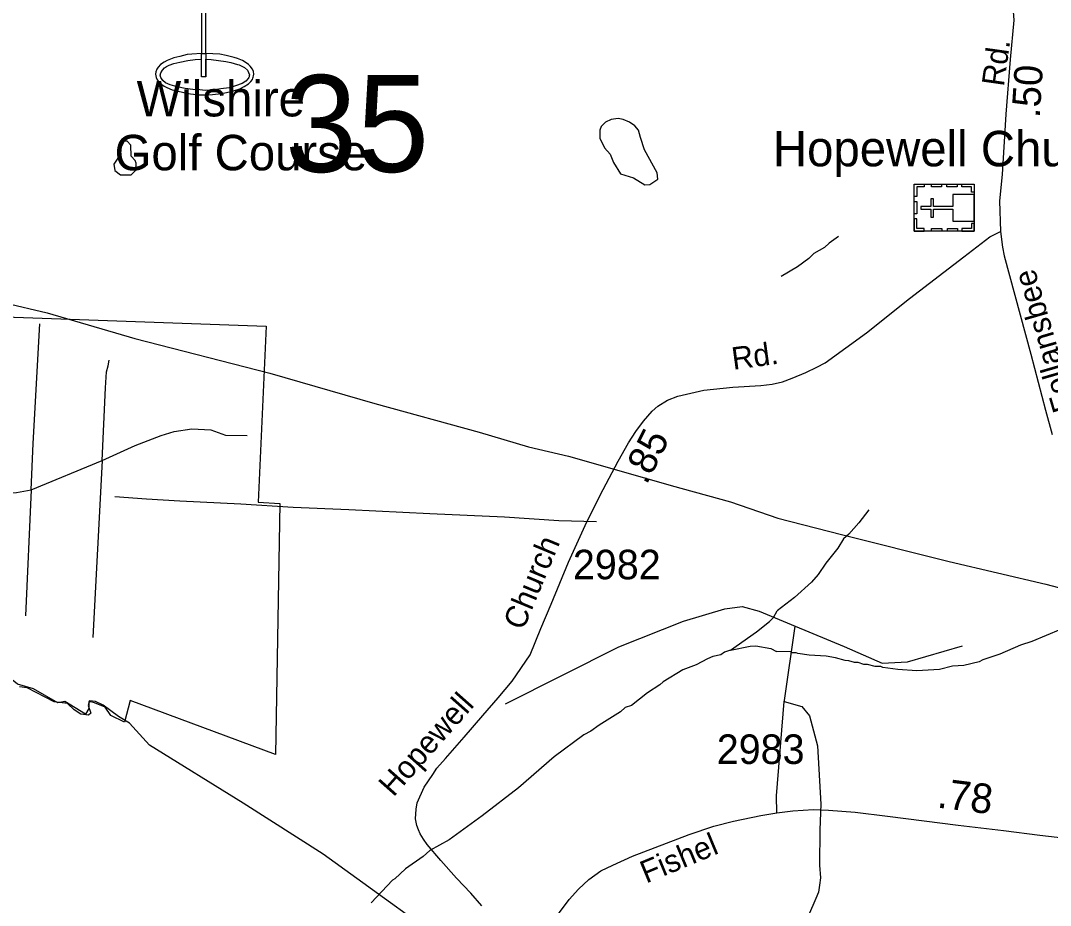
# Model space of a CAD drawing. Extents: x 1547597 to 1699558, y 810033 to 920809.
# Drawn here: x 1627167 to 1631529, y 823409 to 827154 of the extents above; entities that cross this region are included whole.
import ezdxf

# ---------------------------------------------------------------- set-up
doc = ezdxf.new("R2010")
doc.units = 0
for name, color, linetype in [('Exist Boundary Political City Limit New', 7, 'Continuous'), ('Exist Cultural Church with Cemetery CELL', 7, 'Continuous'), ('Exist Cultural Church with Cemetery Label', 7, 'Continuous'), ('Exist Cultural Recreational Golf Course CELL', 7, 'Continuous'), ('Exist Cultural Recreational Golf Course Label', 7, 'Continuous'), ('Exist Hydrographic Creek Single Shore', 7, 'Continuous'), ('Exist Hydrographic Misc Water Feature', 7, 'Continuous'), ('Exist Road Non-System Type 51', 7, 'Continuous'), ('Exist Road Secondary Mileage Hundredths English Label', 7, 'Continuous'), ('Exist Road Secondary Structure Standard Bridge Number Label', 7, 'Continuous'), ('Exist Road Secondary Type 51 Attributed', 7, 'Continuous'), ('Exist Road Secondary Type 51 Label', 7, 'Continuous'), ('Exist Road Secondary Type 51 Number Label', 7, 'Continuous'), ('Exist Utilities Electrical Transmission Line', 7, 'Continuous'), ('Map Preparation Boundary City Limit Buffer Line', 7, 'Continuous')]:
    doc.layers.add(name, color=color, linetype=linetype)

msp = doc.modelspace()

# ---------------------------------------------------------------- linework, layer by layer
at = {"layer": 'Exist Boundary Political City Limit New'}
msp.add_lwpolyline([(1627100, 825900), (1628206.7, 825861), (1628172.5, 825115), (1628265.2, 825110.1), (1628245.7, 824047.1), (1627631.4, 824276.3), (1627607, 824183.6), (1627548.5, 824212.9), (1627524.2, 824247), (1627480.3, 824266.5), (1627455.9, 824271.4), (1627455.9, 824242.2), (1627441.3, 824217.8), (1627353.5, 824271.4), (1627324.3, 824266.5), (1627221.9, 824325.1), (1627153.7, 824344.6), (1627031.8, 824442.1), (1627100, 825900)], dxfattribs=at)
at = {"layer": 'Exist Cultural Church with Cemetery CELL'}
for points in [[(1630951.1, 826262.4), (1630951.1, 826461.4), (1631205.8, 826461.4), (1631205.8, 826262.4)], [(1630994.5, 826461.5), (1630994.5, 826450.2), (1630962.3, 826450.2), (1630962.3, 826409.6), (1630951.2, 826409.6), (1630951.2, 826461.5)], [(1631067.6, 826450.1), (1631024.3, 826450.1), (1631024.3, 826461.5), (1631067.6, 826461.5)], [(1631133.5, 826450.1), (1631090.2, 826450.1), (1631090.2, 826461.5), (1631133.5, 826461.5)], [(1631205.8, 826428.3), (1631194.3, 826428.3), (1631194.3, 826450.3), (1631153.9, 826450.3), (1631153.9, 826461.4), (1631205.8, 826461.4)], [(1631205.7, 826305.5), (1631205.7, 826417.6), (1631115.2, 826417.6), (1631115.1, 826366.9), (1631033.7, 826366.8), (1631033.7, 826399.8), (1631022.7, 826399.8), (1631022.7, 826366.8), (1630980.4, 826366.9), (1630980.4, 826355.3), (1631022.7, 826355.2), (1631022.7, 826322.1), (1631033.7, 826322.1), (1631033.7, 826355.2), (1631115.1, 826355.3), (1631115.2, 826305.5)], [(1630951.1, 826336.4), (1630951.1, 826388.3), (1630962.5, 826388.3), (1630962.5, 826336.4)], [(1630994.4, 826262.4), (1630994.4, 826273.7), (1630962.2, 826273.7), (1630962.3, 826314.3), (1630951.1, 826314.3), (1630951.1, 826262.4)], [(1631205.7, 826295.4), (1631194.2, 826295.4), (1631194.2, 826273.4), (1631153.8, 826273.4), (1631153.8, 826262.3), (1631205.7, 826262.3)], [(1631068.6, 826262.3), (1631025.3, 826262.3), (1631025.3, 826273.7), (1631068.6, 826273.7)], [(1631135.8, 826262.3), (1631092.5, 826262.3), (1631092.5, 826273.7), (1631135.8, 826273.7)]]:
    msp.add_lwpolyline(points, close=True, dxfattribs=at)
at = {"layer": 'Exist Cultural Recreational Golf Course CELL'}
msp.add_lwpolyline([(1627932.4, 827194.1), (1627932.4, 827015.2), (1627950.8, 827015.2), (1627950.8, 826990.2), (1627950.8, 826915.2), (1627950.8, 826990.2), (1627974.5, 826988.6), (1628005, 826985.3), (1628036.5, 826981.3), (1628057.7, 826977), (1628085.5, 826968.7), (1628092.5, 826966.6), (1628115.1, 826954.8), (1628127.2, 826943.9), (1628132.6, 826934.3), (1628135.6, 826924.8), (1628135.4, 826920.4), (1628134.3, 826916.3), (1628133.3, 826913), (1628131.1, 826909.2), (1628120.4, 826897.3), (1628104.7, 826887.8), (1628077.3, 826877.4), (1628050.8, 826869.9), (1628015.2, 826864.4), (1627988.2, 826860.4), (1627948.1, 826858.5), (1627925.6, 826860.4), (1627896.6, 826861.9), (1627863.5, 826866.4), (1627829.5, 826873.9), (1627800.4, 826882.4), (1627780.9, 826891), (1627768.9, 826900.5), (1627760.4, 826912.5), (1627757.9, 826922.5), (1627760.4, 826933.5), (1627767.4, 826944.5), (1627775.9, 826954), (1627785, 826959.3), (1627796.4, 826965.1), (1627815.6, 826971.6), (1627841.7, 826978.6), (1627874.5, 826984.6), (1627906.6, 826988.6), (1627932.4, 826990.2), (1627932.4, 827015.2), (1627950.8, 827015.2), (1627950.8, 826915.2), (1627932.4, 826915.2), (1627932.4, 826990.2), (1627932.4, 827015.2), (1627891.9, 827011.5), (1627872.4, 827009.7), (1627841.6, 827002.5), (1627816.1, 826996.2), (1627787.8, 826985.2), (1627775.4, 826978.1), (1627759.6, 826968.3), (1627749.4, 826957.3), (1627743.1, 826949), (1627739.1, 826936.8), (1627738.1, 826927), (1627740.9, 826912.5), (1627743.6, 826905.5), (1627752.6, 826893.2), (1627760.9, 826886.2), (1627774.8, 826876.6), (1627786.5, 826870.8), (1627809.1, 826861.3), (1627827.9, 826856.3), (1627858.1, 826849), (1627886.2, 826843.5), (1627922.6, 826840.1), (1627946.1, 826839.1), (1627979.9, 826841.1), (1628005.2, 826843.6), (1628031.6, 826848.3), (1628063.7, 826854.8), (1628094.7, 826865.3), (1628114.1, 826875.2), (1628132.6, 826886.5), (1628142.4, 826896.5), (1628148.4, 826904.7), (1628151, 826910.2), (1628152.4, 826914.3), (1628153.8, 826920.7), (1628154.7, 826927.5), (1628153.2, 826938.8), (1628148.7, 826949), (1628138.8, 826961.7), (1628132.5, 826968.4), (1628117.7, 826978.2), (1628106, 826985), (1628085.2, 826993.5), (1628070.9, 826997.5), (1628037.9, 827006.2), (1628010.3, 827011.2), (1627950.8, 827015.2), (1627950.8, 827329.1)], dxfattribs=at)
at = {"layer": 'Exist Hydrographic Creek Single Shore'}
msp.add_lwpolyline([(1629085.4, 823165.6), (1628448.6, 823625.6), (1628109.6, 823841.9), (1627712.3, 824086.1), (1627628.4, 824180.1), (1627580.8, 824207.8), (1627516.6, 824256.6), (1627484.4, 824271.5), (1627459, 824274.8), (1627452.9, 824254.9), (1627464, 824221.7), (1627454, 824213.9), (1627422.4, 824218.3), (1627393.1, 824236.6), (1627365.9, 824262.6), (1627309.4, 824270.4), (1627194.3, 824329.7), (1627162.7, 824333.5)], dxfattribs=at)
at = {"layer": 'Exist Hydrographic Misc Water Feature'}
for points in [[(1629792.3, 826659.4), (1629784.2, 826689.9), (1629768.8, 826708.5), (1629746.4, 826724.3), (1629718.9, 826735.9), (1629697.1, 826739), (1629668.8, 826735.8), (1629643.8, 826723.3), (1629625.3, 826705.9), (1629620.2, 826689.6), (1629620.5, 826656.4), (1629640.6, 826615.9), (1629664.4, 826588), (1629677.4, 826553.2), (1629707.2, 826505.5), (1629762.2, 826488.6), (1629811.4, 826459), (1629831.9, 826459.5), (1629866, 826482.5), (1629862.8, 826509.4), (1629809.4, 826607.5), (1629792.3, 826659.4)], [(1627587.6, 826608), (1627578, 826571.2), (1627561.1, 826546.8), (1627565.4, 826518.9), (1627590.1, 826501.5), (1627634.6, 826500.6), (1627654.4, 826521.2), (1627655.6, 826549.9), (1627652.4, 826561.6), (1627635.1, 826579.6), (1627633.1, 826626.7), (1627617.9, 826643.8), (1627605, 826643.6), (1627587.6, 826608)], [(1630631.5, 826239.4), (1630591.3, 826211.7), (1630571.2, 826194), (1630527.1, 826168.3), (1630505, 826146.5), (1630456.8, 826110.9), (1630388.7, 826070.3)], [(1630759.2, 825083.2), (1630716.9, 825027.6), (1630674.5, 824980), (1630652.5, 824960.2), (1630628.2, 824920.4), (1630577.9, 824856.9), (1630545.5, 824809.2), (1630517.3, 824777.4), (1630444.9, 824712), (1630370.9, 824655.4)], [(1630174.3, 824489.6), (1630283.6, 824566.8), (1630338.3, 824610.1), (1630356.4, 824627.1), (1630370.9, 824655.4)], [(1631570.8, 824577.1), (1631450.6, 824526.1), (1631402.6, 824510.5), (1631314.4, 824471.3), (1631242.2, 824447.8), (1631226.2, 824440), (1631162.2, 824424.5), (1631114.2, 824420.9), (1631058.2, 824407.3), (1630962.2, 824402.1), (1630882.4, 824406.8), (1630818.5, 824415.3), (1630810.5, 824419.3), (1630786.5, 824419.5), (1630754.6, 824427.8), (1630738.6, 824427.9), (1630714.7, 824436.1), (1630698.7, 824436.2), (1630674.8, 824444.4), (1630658.9, 824444.6), (1630619, 824456.9), (1630579.1, 824463.2), (1630507.1, 824467.7), (1630459.2, 824474.1), (1630451.2, 824478.2), (1630435.3, 824478.3), (1630427.3, 824482.3), (1630368.7, 824483.1)], [(1630174.3, 824489.6), (1630257, 824506.2), (1630280.9, 824506.9), (1630344.7, 824496.5), (1630368.7, 824483.1)], [(1630174.3, 824489.6), (1630148.7, 824480.9), (1630132.5, 824469.4), (1630098.3, 824461.4), (1630076.3, 824452.4), (1630028, 824427.5), (1629971.7, 824406.2), (1629889.1, 824355.3), (1629874.9, 824341.5), (1629822.4, 824308.2), (1629753.9, 824255.2), (1629727.7, 824245.6), (1629707.4, 824227.9), (1629616.8, 824171.2), (1629582.4, 824145.6), (1629552.2, 824130.1), (1629427, 824037.8), (1629275.4, 823906), (1629121.8, 823788.2), (1628982.4, 823686.1), (1628899.9, 823641.3), (1628871.6, 823615.7), (1628796.9, 823562.8), (1628752.4, 823521.4), (1628742.3, 823515.5), (1628651.5, 823419.2)]]:
    msp.add_lwpolyline(points, dxfattribs=at)
at = {"layer": 'Exist Road Non-System Type 51'}
for p, q in [((1627211.4, 825167.8), (1627512.2, 825292.4)), ((1627512.2, 825292.4), (1627472.9, 824542.1)), ((1627211.4, 825167.8), (1627187.8, 824634.1))]:
    msp.add_line(p, q, dxfattribs=at)
for points in [[(1627211.4, 825167.8), (1627220.4, 825363.1), (1627248.4, 825869.8)], [(1627512.2, 825292.4), (1627526.8, 825598.7), (1627531.2, 825667.8), (1627536.9, 825692.4), (1627542.5, 825717.1)], [(1627512.2, 825292.4), (1627651.3, 825355.8), (1627762.4, 825397.3), (1627817.4, 825414.1), (1627891.5, 825426.5), (1627972.3, 825422), (1628034, 825399.5), (1628126, 825397.3)], [(1626989.2, 825152.1), (1627082.3, 825155.4), (1627149.7, 825156.6), (1627211.4, 825167.8)], [(1629606.5, 825031.7), (1629446.7, 825036.1), (1629216.9, 825051.4), (1628899.8, 825066.2), (1628556.4, 825083.4), (1628320.8, 825093), (1628099.2, 825106.3), (1627841.7, 825120.1), (1627700, 825128.2), (1627566.3, 825138.1)], [(1629220.5, 824261.4), (1629700.4, 824502.7), (1629974.3, 824611.3), (1630149, 824664.2), (1630222.6, 824673.4), (1630295, 824653.7), (1630447.2, 824590.5)], [(1630400.4, 824271.3), (1630401.7, 824275.9), (1630447.2, 824590.5)], [(1630447.2, 824590.5), (1630655.6, 824503.8), (1630816, 824434.1), (1630922.8, 824439.6), (1631156.6, 824507.9)], [(1630370.2, 823799.7), (1630368, 823872.2), (1630400.4, 824271.3)], [(1630400.4, 824271.3), (1630475.6, 824249.9), (1630508.6, 824210.3), (1630541.9, 824084.3), (1630556.6, 823836.7)], [(1630556.6, 823836.7), (1630552.6, 823728.9), (1630550, 823578.9), (1630555.1, 823524.8), (1630550.5, 823494.8), (1630546, 823464.9), (1630535.5, 823437.1), (1630472.9, 823294.3), (1630400.1, 823125.5)]]:
    msp.add_lwpolyline(points, dxfattribs=at)
at = {"layer": 'Exist Road Secondary Type 51 Attributed'}
for points in [[(1631168.9, 828353.4), (1631202.5, 828109.4), (1631270.2, 827776.2), (1631327.2, 827497.8), (1631361.9, 827305.1), (1631374.1, 827155.9), (1631358.4, 826988.6), (1631339.3, 826757.7), (1631323.7, 826502.5), (1631313.2, 826390.7), (1631317.2, 826261.2)], [(1629120.9, 823407.1), (1629073.2, 823459.7), (1629013.4, 823523.9), (1628946.4, 823598.1), (1628888.3, 823666.2), (1628872.8, 823688.9), (1628859.5, 823711.6), (1628851.7, 823728.2), (1628844.5, 823747.1), (1628839.5, 823775.3), (1628842.3, 823815.7), (1628846.5, 823843), (1628875.4, 823908.9), (1628912.4, 823962.5), (1628929.8, 823989.6), (1628965.8, 824030.6), (1629045.6, 824120.9), (1629124.2, 824211.7), (1629189.5, 824286.5), (1629249.3, 824357.9), (1629324.4, 824469.6), (1629369.7, 824580.9), (1629413.8, 824683), (1629487.5, 824861.3), (1629536.2, 824969.8), (1629565.6, 825032.4), (1629634.2, 825168.6), (1629698.5, 825288.8), (1629742.2, 825366.9), (1629772.1, 825414), (1629804.8, 825458.3), (1629842.4, 825500.9), (1629865.7, 825521.9), (1629906.1, 825546.9), (1629951, 825564.6), (1630061, 825589.5), (1630183, 825601.7), (1630302.1, 825608.9), (1630350.8, 825615), (1630393.5, 825624.4), (1630435, 825639.9), (1630492, 825664.3), (1630538.6, 825687.5), (1630574.2, 825705.2), (1630750.3, 825831.7), (1630931.1, 825976.9), (1631161.6, 826153.8), (1631272.3, 826238), (1631317.2, 826261.2)], [(1631317.2, 826261.2), (1631325.5, 826194.2), (1631332.7, 826157.7), (1631445.6, 825742.4), (1631508.2, 825505.3), (1631535.9, 825401.8)], [(1629319.1, 823192.7), (1629388.7, 823287.3), (1629448.7, 823378.8), (1629489.7, 823433.6), (1629530.1, 823477.9), (1629573.3, 823517.8), (1629624.3, 823554.4), (1629674.7, 823579.3), (1629758.8, 823616.9), (1629998.1, 823708.9), (1630103.3, 823743.8), (1630186.9, 823765.3), (1630302.6, 823788.6), (1630370.2, 823799.7), (1630437.8, 823808.5), (1630525.8, 823814.6), (1630588.4, 823811.9), (1630701.9, 823803.6), (1630838.1, 823786.9), (1630994.3, 823767), (1631137.7, 823748.7), (1631329.4, 823724.9), (1631484.4, 823705.5), (1631740.3, 823676.2)]]:
    msp.add_lwpolyline(points, dxfattribs=at)
at = {"layer": 'Exist Utilities Electrical Transmission Line'}
msp.add_lwpolyline([(1627099.3, 825959.2), (1627278.6, 825916.3), (1627650.6, 825808.7), (1628221.7, 825662.1), (1628667.1, 825533.2), (1629108.9, 825412.4), (1629317.8, 825349.3), (1629486.9, 825310.6), (1629749.5, 825234.7), (1629922.6, 825185.9), (1630173.3, 825116.2), (1630374.6, 825047.6), (1630644.2, 824977.9), (1631100.4, 824864.2), (1631508.8, 824768.9), (1631616.5, 824739.5)], dxfattribs=at)
at = {"layer": 'Map Preparation Boundary City Limit Buffer Line'}
msp.add_lwpolyline([(1627100, 825900), (1628206.7, 825861), (1628172.5, 825115), (1628265.2, 825110.1), (1628245.7, 824047.1), (1627631.4, 824276.3), (1627607, 824183.6), (1627548.5, 824212.9), (1627524.2, 824247), (1627480.3, 824266.5), (1627455.9, 824271.4), (1627455.9, 824242.2), (1627441.3, 824217.8), (1627353.5, 824271.4), (1627324.3, 824266.5), (1627221.9, 824325.1), (1627153.7, 824344.6), (1627031.8, 824442.1), (1627100, 825900)], dxfattribs=at)

# ---------------------------------------------------------------- texts
at = {"layer": 'Exist Cultural Church with Cemetery Label'}
msp.add_text('Hopewell Church', height=150, dxfattribs=at).set_placement((1630353.1, 826537.1))
at = {"layer": 'Exist Cultural Recreational Golf Course Label'}
for s, p in [('Wilshire', (1627658, 826748.4)), ('Golf Course', (1627564.8, 826520.2))]:
    msp.add_text(s, height=150, rotation=0, dxfattribs=at).set_placement(p)
at = {"layer": 'Exist Road Secondary Mileage Hundredths English Label'}
for s, height, rotation, p in [('.50', 120, 86.2652, (1631483.1, 826740)), ('.85', 120, 63.4488, (1629817.8, 825185.5)), ('.78', 125, 352.9157, (1631045.8, 823823.1))]:
    msp.add_text(s, height=height, rotation=rotation, dxfattribs=at).set_placement(p)
at = {"layer": 'Exist Road Secondary Structure Standard Bridge Number Label'}
msp.add_text('35', height=410.1, dxfattribs=at).set_placement((1628286.7, 826513.3))
at = {"layer": 'Exist Road Secondary Type 51 Label'}
for s, rotation, p in [('Rd.', 81.9835, (1631331.3, 826872.3)), ('Follansbee', 106.1884, (1631634.5, 825511.8)), ('Rd.', 7.7003, (1630185.1, 825675.4)), ('Church', 67.3578, (1629295.6, 824568.8)), ('Hopewell', 48.4974, (1628745.9, 823864.2)), ('Fishel', 22.5521, (1629816.1, 823500.5))]:
    msp.add_text(s, height=95, rotation=rotation, dxfattribs=at).set_placement(p)
at = {"layer": 'Exist Road Secondary Type 51 Number Label'}
for s, p in [('2982', (1629506.1, 824789)), ('2983', (1630115.4, 824007.2))]:
    msp.add_text(s, height=125, dxfattribs=at).set_placement(p)

doc.saveas('drawing.dxf')
